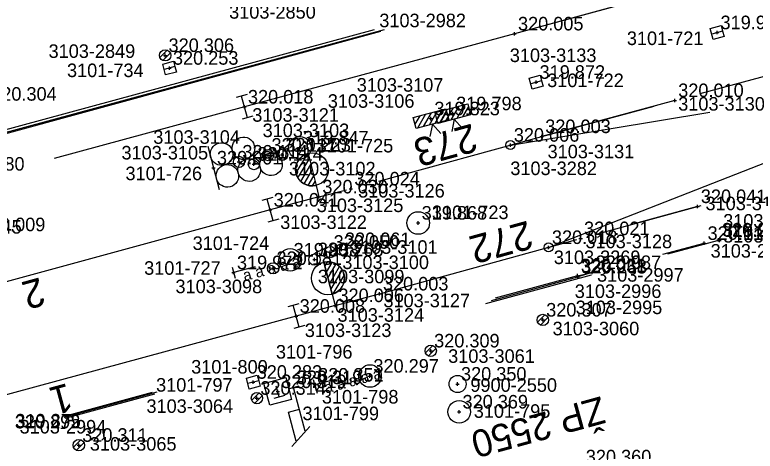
# Model space of a CAD drawing. Extents: x -821875 to -821475, y -1070280 to -1069975.
# Drawn here: x -821680.94 to -821648.14, y -1070237.36 to -1070218.01 of the extents above; entities that cross this region are included whole.
import ezdxf

# ---------------------------------------------------------------- set-up
doc = ezdxf.new("R2010")
doc.units = 0
for name, color, linetype in [('Vrstva 1', 7, 'Continuous'), ('Vrstva 10', 7, 'Continuous'), ('Vrstva 14', 7, 'Continuous'), ('Vrstva 2', 7, 'Continuous'), ('Vrstva 28', 7, 'Continuous'), ('Vrstva 3', 7, 'Continuous'), ('Vrstva 33', 7, 'Continuous'), ('Vrstva 36', 7, 'Continuous'), ('Vrstva 4', 7, 'Continuous'), ('Vrstva 43', 7, 'Continuous'), ('Vrstva 6', 7, 'Continuous'), ('Vrstva 60', 7, 'Continuous'), ('Vrstva 61', 7, 'Continuous'), ('Vrstva 63', 7, 'Continuous')]:
    doc.layers.add(name, color=color, linetype=linetype)

# ---------------------------------------------------------------- blocks, each defined once
blk = doc.blocks.new('BOD')
at = {"layer": 'Vrstva 3'}
for p, q in [((-0.15, 0), (0.15, 0)), ((0, -0.15), (0, 0.15))]:
    blk.add_line(p, q, dxfattribs=at)

msp = doc.modelspace()

# ---------------------------------------------------------------- linework, layer by layer
at = {"layer": 'Vrstva 1'}
for points in [[(-821651.475, -1070216.85), (-821652.883, -1070217.232), (-821658.799, -1070218.855), (-821670.76, -1070222.095)], [(-821670.76, -1070222.095), (-821679.19, -1070224.389)], [(-821667.464, -1070226.079), (-821669.621, -1070226.661), (-821739.032, -1070245.599)], [(-821666.751, -1070230.896), (-821668.47, -1070231.368), (-821683.884, -1070235.554)]]:
    msp.add_lwpolyline(points, dxfattribs=at)
at = {"layer": 'Vrstva 10'}
for p, q in [((-821668.353, -1070234.469), (-821668.835, -1070234.599)), ((-821668.07, -1070236.464), (-821668.594, -1070234.534)), ((-821667.868, -1070236.254), (-821668.662, -1070237.143))]:
    msp.add_line(p, q, dxfattribs=at)
msp.add_lwpolyline([(-821668.467, -1070236.909), (-821668.814, -1070235.63), (-821668.332, -1070235.499)], dxfattribs=at)
at = {"layer": 'Vrstva 14'}
for p, q in [((-821768.204, -1070246.736), (-821665.012, -1070218.658)), ((-821664.58, -1070218.678), (-821684.759, -1070224.159)), ((-821684.647, -1070224.184), (-821664.729, -1070218.735)), ((-821652.238, -1070228.618), (-821650.402, -1070228.139)), ((-821649.604, -1070227.969), (-821652.024, -1070228.629)), ((-821654.307, -1070229.158), (-821654.273, -1070229.149)), ((-821655.406, -1070229.55), (-821660.083, -1070230.825)), ((-821656.016, -1070229.575), (-821655.36, -1070229.432)), ((-821655.36, -1070229.432), (-821655.995, -1070229.628)), ((-821659.817, -1070230.674), (-821655.995, -1070229.628)), ((-821656.016, -1070229.575), (-821659.661, -1070230.576)), ((-821674.858, -1070234.749), (-821678.75, -1070235.818)), ((-821678.744, -1070235.853), (-821674.637, -1070234.729)), ((-821674.752, -1070234.822), (-821678.718, -1070235.903))]:
    msp.add_line(p, q, dxfattribs=at)
at = {"layer": 'Vrstva 2'}
for p, q in [((-821668.481, -1070225.022), (-821667.964, -1070224.161)), ((-821667.945, -1070224.155), (-821667.591, -1070225.575)), ((-821667.945, -1070224.155), (-821667.945, -1070224.155)), ((-821667.945, -1070224.16), (-821667.59, -1070225.58)), ((-821668.456, -1070224.622), (-821668.304, -1070224.368)), ((-821668.396, -1070225.24), (-821667.886, -1070224.39)), ((-821668.273, -1070225.394), (-821667.823, -1070224.644)), ((-821668.123, -1070225.503), (-821667.76, -1070224.898)), ((-821667.948, -1070225.572), (-821667.696, -1070225.152)), ((-821667.746, -1070225.595), (-821667.633, -1070225.406)), ((-821667.59, -1070225.58), (-821667.464, -1070226.079)), ((-821666.883, -1070230.398), (-821667.252, -1070228.982)), ((-821667.252, -1070228.982), (-821666.882, -1070230.398)), ((-821667.204, -1070229.166), (-821667.084, -1070228.96)), ((-821667.137, -1070229.423), (-821666.881, -1070228.985)), ((-821667.07, -1070229.679), (-821666.705, -1070229.056)), ((-821667.004, -1070229.936), (-821666.554, -1070229.17)), ((-821666.937, -1070230.193), (-821666.431, -1070229.331)), ((-821666.829, -1070230.38), (-821666.349, -1070229.561)), ((-821666.882, -1070230.398), (-821666.883, -1070230.398)), ((-821666.883, -1070230.399), (-821666.751, -1070230.896))]:
    msp.add_line(p, q, dxfattribs=at)
for points in [[(-821650.582, -1070221.506), (-821645.043, -1070220.008)], [(-821664.813, -1070225.386), (-821657.592, -1070223.405), (-821652.614, -1070222.056)], [(-821658.984, -1070223.787), (-821650.151, -1070222.334)], [(-821657.296, -1070228.321), (-821643.839, -1070223.049)], [(-821667.464, -1070226.079), (-821666.238, -1070225.773)], [(-821655.124, -1070227.723), (-821650.7, -1070226.506), (-821650.532, -1070226.46)], [(-821666.751, -1070230.896), (-821664.781, -1070230.381), (-821656.047, -1070227.977)]]:
    msp.add_lwpolyline(points, dxfattribs=at)
for centre, radius in [((-821658.984, -1070223.787), 0.2), ((-821667.768, -1070224.866), 0.731), ((-821657.296, -1070228.321), 0.2), ((-821667.068, -1070229.687), 0.731)]:
    msp.add_circle(centre, radius, dxfattribs=at)
for centre, start, end in [((-821667.768, -1070224.866), 104.0553, 284.0162), ((-821667.067, -1070229.691), 284.67, 104.6309)]:
    msp.add_arc(centre, 0.732, start, end, dxfattribs=at)
at = {"layer": 'Vrstva 28'}
for p, q in [((-821661.012, -1070221.994), (-821661.364, -1070222.606)), ((-821662.236, -1070222.285), (-821662.588, -1070222.897)), ((-821661.98, -1070222.216), (-821662.332, -1070222.828)), ((-821662.291, -1070222.339), (-821662.316, -1070222.382)), ((-821662.035, -1070222.27), (-821662.247, -1070222.637)), ((-821661.779, -1070222.201), (-821662.132, -1070222.814)), ((-821661.812, -1070222.301), (-821662.076, -1070222.759)), ((-821661.524, -1070222.132), (-821661.876, -1070222.744)), ((-821661.268, -1070222.063), (-821661.62, -1070222.675)), ((-821660.844, -1070222.079), (-821661.108, -1070222.537)), ((-821660.775, -1070222.335), (-821660.852, -1070222.468)), ((-821663.259, -1070222.561), (-821663.284, -1070222.604)), ((-821663.003, -1070222.492), (-821663.215, -1070222.859)), ((-821662.747, -1070222.423), (-821663.1, -1070223.036)), ((-821662.492, -1070222.354), (-821662.844, -1070222.966)), ((-821661.743, -1070222.557), (-821661.82, -1070222.69)), ((-821669.741, -1070224.23), (-821669.691, -1070224.23)), ((-821669.124, -1070224.224), (-821669.074, -1070224.224)), ((-821671.031, -1070224.534), (-821670.981, -1070224.534)), ((-821670.369, -1070224.628), (-821670.319, -1070224.628)), ((-821666.99, -1070228.531), (-821666.94, -1070228.531)), ((-821666.489, -1070228.414), (-821666.439, -1070228.414)), ((-821667.688, -1070228.862), (-821667.638, -1070228.862)), ((-821669.518, -1070229.249), (-821669.468, -1070229.249))]:
    msp.add_line(p, q, dxfattribs=at)
for points in [[(-821660.747, -1070222.44), (-821662.195, -1070222.83), (-821662.325, -1070222.348), (-821660.877, -1070221.958)], [(-821661.715, -1070222.662), (-821663.163, -1070223.052), (-821663.293, -1070222.57), (-821661.845, -1070222.18)]]:
    msp.add_lwpolyline(points, close=True, dxfattribs=at)
for points in [[(-821660.747, -1070222.44), (-821662.195, -1070222.83), (-821662.325, -1070222.348), (-821660.877, -1070221.958), (-821660.747, -1070222.44)], [(-821661.715, -1070222.662), (-821663.163, -1070223.052), (-821663.293, -1070222.57), (-821661.845, -1070222.18), (-821661.715, -1070222.662)], [(-821661.1, -1070223.053), (-821661.471, -1070222.635), (-821661.582, -1070223.183)], [(-821662.068, -1070223.275), (-821662.439, -1070222.857), (-821662.55, -1070223.405)]]:
    msp.add_lwpolyline(points, dxfattribs=at)
for centre in [(-821669.716, -1070224.23), (-821669.099, -1070224.224), (-821671.006, -1070224.534), (-821670.344, -1070224.628), (-821666.464, -1070228.414), (-821666.965, -1070228.531), (-821667.663, -1070228.862), (-821669.493, -1070229.249)]:
    msp.add_circle(centre, 0.25, dxfattribs=at)
at = {"layer": 'Vrstva 3'}
for p, q in [((-821670.65, -1070221.547), (-821671.132, -1070221.678)), ((-821670.629, -1070222.577), (-821670.891, -1070221.613)), ((-821670.388, -1070222.512), (-821670.87, -1070222.643)), ((-821669.51, -1070226.113), (-821669.993, -1070226.244)), ((-821669.49, -1070227.144), (-821669.752, -1070226.178)), ((-821669.249, -1070227.078), (-821669.732, -1070227.209)), ((-821668.36, -1070230.82), (-821668.843, -1070230.951)), ((-821668.338, -1070231.851), (-821668.602, -1070230.885)), ((-821668.097, -1070231.785), (-821668.58, -1070231.916))]:
    msp.add_line(p, q, dxfattribs=at)
at = {"layer": 'Vrstva 33'}
for p, q in [((-821669.224, -1070234.95), (-821669.354, -1070234.466)), ((-821668.982, -1070234.884), (-821669.465, -1070235.015))]:
    msp.add_line(p, q, dxfattribs=at)
msp.add_lwpolyline([(-821668.676, -1070235.061), (-821669.642, -1070235.321), (-821669.902, -1070234.355), (-821668.936, -1070234.095), (-821668.676, -1070235.061)], dxfattribs=at)
at = {"layer": 'Vrstva 36'}
for p, q in [((-821674.506, -1070219.902), (-821674.184, -1070219.579)), ((-821674.376, -1070220.037), (-821674.049, -1070219.71)), ((-821657.78, -1070231.629), (-821657.456, -1070231.306)), ((-821657.65, -1070231.764), (-821657.322, -1070231.436)), ((-821662.744, -1070232.998), (-821662.42, -1070232.675)), ((-821662.614, -1070233.133), (-821662.286, -1070232.806)), ((-821670.442, -1070235.095), (-821670.12, -1070234.772)), ((-821670.312, -1070235.23), (-821669.985, -1070234.902)), ((-821678.33, -1070237.18), (-821678.006, -1070236.857)), ((-821678.2, -1070237.315), (-821677.872, -1070236.988))]:
    msp.add_line(p, q, dxfattribs=at)
for centre in [(-821674.276, -1070219.81), (-821657.549, -1070231.537), (-821662.513, -1070232.906), (-821670.212, -1070235.003), (-821678.099, -1070237.088)]:
    msp.add_circle(centre, 0.25, dxfattribs=at)
at = {"layer": 'Vrstva 4'}
for p, q in [((-821652.883, -1070217.232), (-821658.799, -1070218.855)), ((-821651.702, -1070221.809), (-821657.592, -1070223.405)), ((-821650.7, -1070226.506), (-821653.661, -1070227.32))]:
    msp.add_line(p, q, dxfattribs=at)
at = {"layer": 'Vrstva 43'}
for points in [[(-821649.587, -1070218.735), (-821649.521, -1070218.976), (-821650.004, -1070219.107), (-821650.135, -1070218.624), (-821649.652, -1070218.493), (-821649.587, -1070218.735), (-821650.069, -1070218.865)], [(-821673.841, -1070220.311), (-821673.777, -1070220.553), (-821674.26, -1070220.68), (-821674.387, -1070220.197), (-821673.904, -1070220.07), (-821673.841, -1070220.311), (-821674.323, -1070220.439)], [(-821657.602, -1070220.935), (-821657.536, -1070221.176), (-821658.019, -1070221.307), (-821658.15, -1070220.824), (-821657.667, -1070220.693), (-821657.602, -1070220.935), (-821658.084, -1070221.065)], [(-821670.132, -1070234.229), (-821670.067, -1070234.471), (-821670.551, -1070234.601), (-821670.681, -1070234.117), (-821670.197, -1070233.987), (-821670.132, -1070234.229), (-821670.616, -1070234.359)]]:
    msp.add_lwpolyline(points, dxfattribs=at)
for centre in [(-821668.316, -1070223.911), (-821663.066, -1070227.24), (-821668.736, -1070228.877), (-821665.204, -1070234.023), (-821661.256, -1070235.612)]:
    msp.add_circle(centre, 0.5, dxfattribs=at)
at = {"layer": 'Vrstva 6'}
for p, q in [((-821672.39, -1070223.831), (-821672.134, -1070224.797)), ((-821672.134, -1070224.797), (-821671.878, -1070225.763)), ((-821671.312, -1070229.197), (-821671.182, -1070229.679)), ((-821670.291, -1070229.18), (-821671.247, -1070229.438)), ((-821667.716, -1070234.178), (-821667.584, -1070234.66)), ((-821666.694, -1070234.159), (-821667.65, -1070234.419)), ((-821667.65, -1070234.419), (-821667.551, -1070234.785))]:
    msp.add_line(p, q, dxfattribs=at)
for centre in [(-821671.778, -1070224.186), (-821670.811, -1070223.93), (-821669.588, -1070224.64), (-821671.522, -1070225.153), (-821670.555, -1070224.897)]:
    msp.add_ellipse(centre, major_axis=(0.484, 0.128), ratio=0.999505, dxfattribs=at)
at = {"layer": 'Vrstva 63'}
msp.add_line((-821661.299, -1070234.371), (-821661.347, -1070234.383), dxfattribs=at)
msp.add_circle((-821661.323, -1070234.377), 0.378, dxfattribs=at)

# ---------------------------------------------------------------- block references
at = {"layer": 'Vrstva 60', "xscale": 0.5, "yscale": 0.5}
for p in [(-821649.828, -1070218.8), (-821658.799, -1070218.855), (-821674.276, -1070219.81), (-821674.082, -1070220.375), (-821657.843, -1070221), (-821651.702, -1070221.809), (-821670.76, -1070222.095), (-821661.536, -1070222.394), (-821662.504, -1070222.616), (-821657.592, -1070223.405), (-821668.316, -1070223.911), (-821658.984, -1070223.787), (-821669.716, -1070224.23), (-821669.099, -1070224.224), (-821671.006, -1070224.534), (-821670.344, -1070224.628), (-821672.134, -1070224.797), (-821666.047, -1070225.725), (-821667.464, -1070226.079), (-821669.621, -1070226.661), (-821650.7, -1070226.506), (-821663.066, -1070227.24), (-821655.874, -1070227.929), (-821649.763, -1070227.989), (-821657.296, -1070228.321), (-821650.402, -1070228.139), (-821649.726, -1070228.01), (-821666.965, -1070228.531), (-821666.464, -1070228.414), (-821668.736, -1070228.877), (-821667.663, -1070228.862), (-821669.493, -1070229.249), (-821671.247, -1070229.438), (-821656.016, -1070229.575), (-821655.995, -1070229.628), (-821655.36, -1070229.432), (-821664.781, -1070230.381), (-821666.751, -1070230.896), (-821668.47, -1070231.368), (-821657.549, -1070231.537), (-821662.513, -1070232.906), (-821665.204, -1070234.023), (-821670.374, -1070234.294), (-821668.594, -1070234.534), (-821667.65, -1070234.419), (-821661.323, -1070234.377), (-821669.289, -1070234.708), (-821670.212, -1070235.003), (-821661.256, -1070235.612), (-821678.099, -1070237.088)]:
    msp.add_blockref('BOD', p, dxfattribs=at)

# ---------------------------------------------------------------- texts
at = {"layer": 'Vrstva 1'}
for s, rotation, p in [('2', 195.3507, (-821679.815, -1070229.641)), ('1', 195.2344, (-821678.594, -1070234.325))]:
    msp.add_text(s, height=1.25, rotation=rotation, dxfattribs=at).set_placement(p)
at = {"layer": 'Vrstva 2'}
for s, rotation, p in [('273', 195.344, (-821660.672, -1070222.824)), ('272', 195.3916, (-821658.212, -1070227.125))]:
    msp.add_text(s, height=1.25, rotation=rotation, dxfattribs=at).set_placement(p)
at = {"layer": 'Vrstva 6'}
for rotation, p in [(15.0984, (-821671.117, -1070229.92)), (15.2391, (-821667.518, -1070234.901))]:
    msp.add_text('  a a a a a', height=0.5, rotation=rotation, dxfattribs=at).set_placement(p)
at = {"layer": 'Vrstva 60'}
for s, p in [('3103-2850', (-821671.443, -1070218.184)), ('3103-2982', (-821664.791, -1070218.563)), ('3101-721', (-821653.826, -1070219.353)), ('3103-2849', (-821679.44, -1070219.923)), ('3103-3133', (-821659.012, -1070220.107)), ('3101-734', (-821678.624, -1070220.774)), ('3101-722', (-821657.356, -1070221.217)), ('3103-3107', (-821665.792, -1070221.42)), ('3103-3106', (-821667.072, -1070222.134)), ('3103-3130', (-821651.552, -1070222.259)), ('3103-3121', (-821670.418, -1070222.752)), ('3103-3103', (-821669.96, -1070223.435)), ('3103-3104', (-821674.802, -1070223.731)), ('3101-725', (-821667.566, -1070224.113)), ('3103-3105', (-821676.211, -1070224.424)), ('3103-3131', (-821657.338, -1070224.373)), ('3103-2980', (-821684.342, -1070224.919)), ('3103-3102', (-821668.793, -1070225.133)), ('3103-3282', (-821658.989, -1070225.117)), ('3101-726', (-821676.034, -1070225.343)), ('3103-3126', (-821665.731, -1070226.112)), ('3103-3125', (-821667.564, -1070226.757)), ('3103-3129', (-821650.344, -1070226.673)), ('3101-723', (-821662.46, -1070227.068)), ('3103-3122', (-821669.18, -1070227.505)), ('3103-2999', (-821649.562, -1070227.446)), ('3103-3000', (-821649.559, -1070228.107)), ('3101-724', (-821673.059, -1070228.434)), ('3103-3128', (-821655.661, -1070228.358)), ('3103-3101', (-821666.046, -1070228.607)), ('3103-2998', (-821650.117, -1070228.775)), ('3103-3269', (-821657.063, -1070229.061)), ('3103-3100', (-821666.43, -1070229.282)), ('3101-727', (-821675.208, -1070229.535)), ('3103-3099', (-821667.513, -1070229.913)), ('3103-2997', (-821655.148, -1070229.841)), ('3103-3098', (-821673.819, -1070230.351)), ('3103-2996', (-821656.136, -1070230.564)), ('3103-3127', (-821664.61, -1070230.976)), ('3103-2995', (-821656.095, -1070231.28)), ('3103-3124', (-821666.642, -1070231.616)), ('3103-3123', (-821668.092, -1070232.294)), ('3103-3060', (-821657.115, -1070232.219)), ('3101-796', (-821669.371, -1070233.25)), ('3103-3061', (-821661.741, -1070233.439)), ('3101-800', (-821673.124, -1070233.914)), ('3101-797', (-821674.679, -1070234.716)), ('9900-2550', (-821660.758, -1070234.723)), ('3101-798', (-821667.335, -1070235.242)), ('3103-3064', (-821675.105, -1070235.657)), ('3101-799', (-821668.195, -1070235.979)), ('3101-795', (-821660.608, -1070235.875)), ('3103-2994', (-821680.724, -1070236.571)), ('3103-3065', (-821677.612, -1070237.329))]:
    msp.add_text(s, height=0.6, dxfattribs=at).set_placement(p)
at = {"layer": 'Vrstva 61'}
for s, p in [('319.919', (-821649.678, -1070218.65)), ('320.005', (-821658.649, -1070218.705)), ('320.306', (-821674.126, -1070219.66)), ('320.253', (-821673.932, -1070220.225)), ('319.872', (-821657.693, -1070220.85)), ('320.304', (-821681.981, -1070221.819)), ('320.018', (-821670.61, -1070221.945)), ('320.010', (-821651.552, -1070221.659)), ('319.798', (-821661.386, -1070222.244)), ('319.823', (-821662.354, -1070222.466)), ('320.003', (-821657.442, -1070223.255)), ('319.847', (-821668.166, -1070223.761)), ('320.006', (-821658.834, -1070223.637)), ('320.117', (-821669.566, -1070224.08)), ('320.223', (-821668.949, -1070224.074)), ('320.114', (-821670.856, -1070224.384)), ('320.114', (-821670.194, -1070224.478)), ('320.001', (-821671.984, -1070224.647)), ('320.024', (-821665.897, -1070225.575)), ('320.030', (-821667.314, -1070225.929)), ('320.041', (-821669.471, -1070226.511)), ('320.041', (-821650.55, -1070226.356)), ('319.868', (-821662.916, -1070227.09)), ('320.045', (-821683.53, -1070227.71)), ('320.009', (-821682.484, -1070227.605)), ('320.021', (-821655.724, -1070227.779)), ('320.272', (-821649.613, -1070227.839)), ('319.906', (-821649.576, -1070227.86)), ('320.018', (-821657.146, -1070228.171)), ('320.110', (-821650.252, -1070227.989)), ('320.050', (-821666.815, -1070228.381)), ('320.061', (-821666.314, -1070228.264)), ('319.938', (-821668.586, -1070228.727)), ('320.268', (-821667.513, -1070228.712)), ('320.181', (-821669.343, -1070229.099)), ('319.972', (-821671.097, -1070229.288)), ('320.031', (-821655.866, -1070229.425)), ('320.268', (-821655.845, -1070229.478)), ('320.087', (-821655.21, -1070229.282)), ('320.003', (-821664.631, -1070230.231)), ('320.006', (-821666.601, -1070230.746)), ('320.008', (-821668.32, -1070231.218)), ('320.307', (-821657.399, -1070231.387)), ('320.309', (-821662.363, -1070232.756)), ('320.297', (-821665.054, -1070233.873)), ('320.283', (-821670.224, -1070234.144)), ('320.319', (-821668.444, -1070234.384)), ('320.351', (-821667.5, -1070234.269)), ('320.350', (-821661.173, -1070234.227)), ('320.319', (-821669.139, -1070234.558)), ('320.314', (-821670.062, -1070234.853)), ('320.369', (-821661.106, -1070235.462)), ('320.292', (-821680.935, -1070236.344)), ('319.875', (-821680.911, -1070236.303)), ('320.311', (-821677.949, -1070236.938)), ('320.360', (-821655.645, -1070237.895))]:
    msp.add_text(s, height=0.6, dxfattribs=at).set_placement(p)
at = {"layer": 'Vrstva 63'}
msp.add_text('ŽP 2550', height=1.2, rotation=195.3539, dxfattribs=at).set_placement((-821654.97, -1070234.911))

doc.saveas('drawing.dxf')
